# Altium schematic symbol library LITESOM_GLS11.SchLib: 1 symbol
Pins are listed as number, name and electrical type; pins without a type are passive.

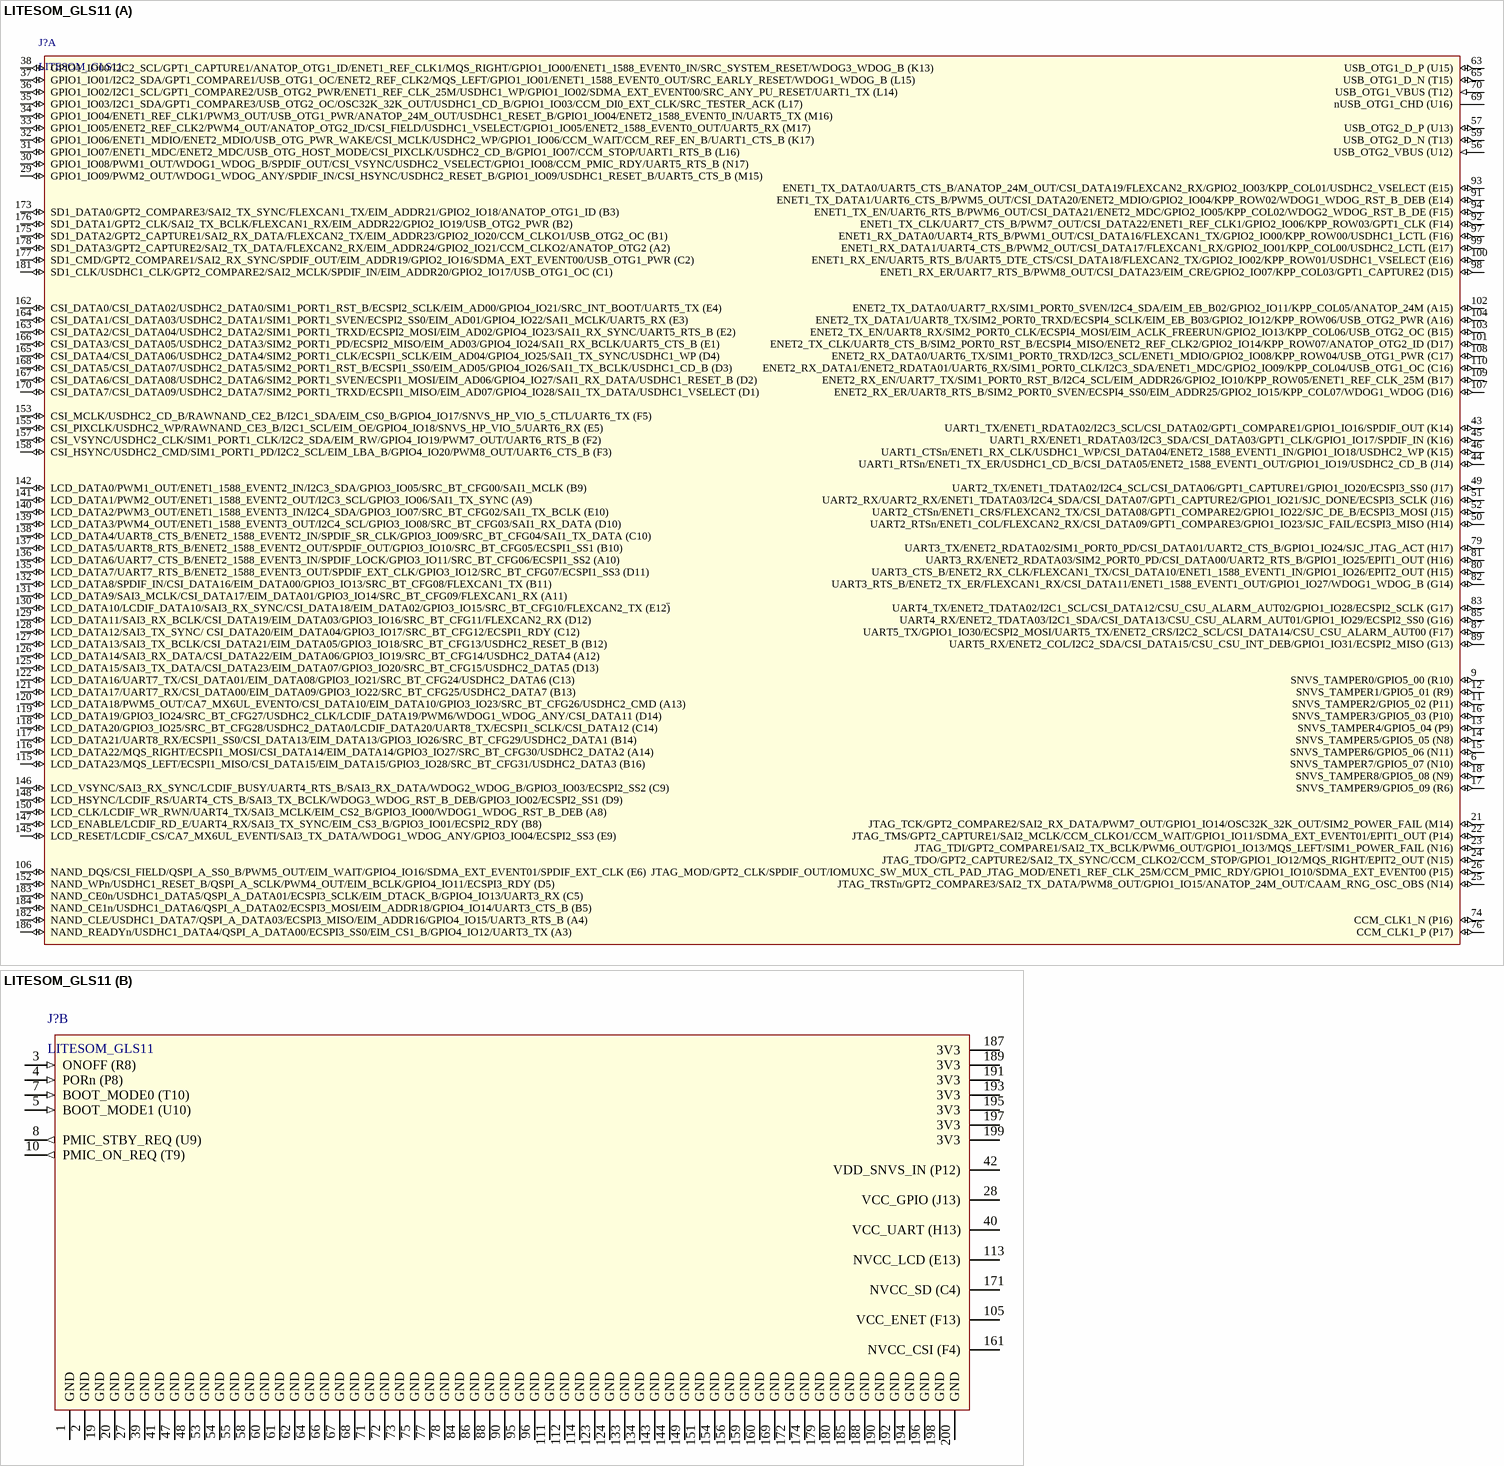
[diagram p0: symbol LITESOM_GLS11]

## LITESOM_GLS11
designator J?
part A pins: 6 SNVS_TAMPER7/GPIO5_07 (N10) (io), 9 SNVS_TAMPER0/GPIO5_00 (R10) (io), 11 SNVS_TAMPER2/GPIO5_02 (P11) (io), 12 SNVS_TAMPER1/GPIO5_01 (R9) (io), 13 SNVS_TAMPER4/GPIO5_04 (P9) (io), 14 SNVS_TAMPER5/GPIO5_05 (N8) (io), 15 SNVS_TAMPER6/GPIO5_06 (N11) (io), 16 SNVS_TAMPER3/GPIO5_03 (P10) (io), 17 SNVS_TAMPER9/GPIO5_09 (R6) (io), 18 SNVS_TAMPER8/GPIO5_08 (N9) (io), 21 JTAG_TCK/GPT2_COMPARE2/SAI2_RX_DATA/PWM7_OUT/GPIO1_IO14/OSC32K_32K_OUT/SIM2_POWER_FAIL (M14) (io), 22 JTAG_TMS/GPT2_CAPTURE1/SAI2_MCLK/CCM_CLKO1/CCM_WAIT/GPIO1_IO11/SDMA_EXT_EVENT01/EPIT1_OUT (P14) (io), 23 JTAG_TDI/GPT2_COMPARE1/SAI2_TX_BCLK/PWM6_OUT/GPIO1_IO13/MQS_LEFT/SIM1_POWER_FAIL (N16) (io), 24 JTAG_TDO/GPT2_CAPTURE2/SAI2_TX_SYNC/CCM_CLKO2/CCM_STOP/GPIO1_IO12/MQS_RIGHT/EPIT2_OUT (N15) (io), 25 JTAG_TRSTn/GPT2_COMPARE3/SAI2_TX_DATA/PWM8_OUT/GPIO1_IO15/ANATOP_24M_OUT/CAAM_RNG_OSC_OBS (N14) (io), 26 JTAG_MOD/GPT2_CLK/SPDIF_OUT/IOMUXC_SW_MUX_CTL_PAD_JTAG_MOD/ENET1_REF_CLK_25M/CCM_PMIC_RDY/GPIO1_IO10/SDMA_EXT_EVENT00 (P15) (io), 29 GPIO1_IO09/PWM2_OUT/WDOG1_WDOG_ANY/SPDIF_IN/CSI_HSYNC/USDHC2_RESET_B/GPIO1_IO09/USDHC1_RESET_B/UART5_CTS_B (M15) (io), 30 GPIO1_IO08/PWM1_OUT/WDOG1_WDOG_B/SPDIF_OUT/CSI_VSYNC/USDHC2_VSELECT/GPIO1_IO08/CCM_PMIC_RDY/UART5_RTS_B (N17) (io), 31 GPIO1_IO07/ENET1_MDC/ENET2_MDC/USB_OTG_HOST_MODE/CSI_PIXCLK/USDHC2_CD_B/GPIO1_IO07/CCM_STOP/UART1_RTS_B (L16) (io), 32 GPIO1_IO06/ENET1_MDIO/ENET2_MDIO/USB_OTG_PWR_WAKE/CSI_MCLK/USDHC2_WP/GPIO1_IO06/CCM_WAIT/CCM_REF_EN_B/UART1_CTS_B (K17) (io), 33 GPIO1_IO05/ENET2_REF_CLK2/PWM4_OUT/ANATOP_OTG2_ID/CSI_FIELD/USDHC1_VSELECT/GPIO1_IO05/ENET2_1588_EVENT0_OUT/UART5_RX (M17) (io), 34 GPIO1_IO04/ENET1_REF_CLK1/PWM3_OUT/USB_OTG1_PWR/ANATOP_24M_OUT/USDHC1_RESET_B/GPIO1_IO04/ENET2_1588_EVENT0_IN/UART5_TX (M16) (io), 35 GPIO1_IO03/I2C1_SDA/GPT1_COMPARE3/USB_OTG2_OC/OSC32K_32K_OUT/USDHC1_CD_B/GPIO1_IO03/CCM_DI0_EXT_CLK/SRC_TESTER_ACK (L17) (io), 36 GPIO1_IO02/I2C1_SCL/GPT1_COMPARE2/USB_OTG2_PWR/ENET1_REF_CLK_25M/USDHC1_WP/GPIO1_IO02/SDMA_EXT_EVENT00/SRC_ANY_PU_RESET/UART1_TX (L14) (io), 37 GPIO1_IO01/I2C2_SDA/GPT1_COMPARE1/USB_OTG1_OC/ENET2_REF_CLK2/MQS_LEFT/GPIO1_IO01/ENET1_1588_EVENT0_OUT/SRC_EARLY_RESET/WDOG1_WDOG_B (L15) (io), 38 GPIO1_IO00/I2C2_SCL/GPT1_CAPTURE1/ANATOP_OTG1_ID/ENET1_REF_CLK1/MQS_RIGHT/GPIO1_IO00/ENET1_1588_EVENT0_IN/SRC_SYSTEM_RESET/WDOG3_WDOG_B (K13) (io), 43 UART1_TX/ENET1_RDATA02/I2C3_SCL/CSI_DATA02/GPT1_COMPARE1/GPIO1_IO16/SPDIF_OUT (K14) (io), 44 UART1_RTSn/ENET1_TX_ER/USDHC1_CD_B/CSI_DATA05/ENET2_1588_EVENT1_OUT/GPIO1_IO19/USDHC2_CD_B (J14) (io), 45 UART1_RX/ENET1_RDATA03/I2C3_SDA/CSI_DATA03/GPT1_CLK/GPIO1_IO17/SPDIF_IN (K16) (io), 46 UART1_CTSn/ENET1_RX_CLK/USDHC1_WP/CSI_DATA04/ENET2_1588_EVENT1_IN/GPIO1_IO18/USDHC2_WP (K15) (io), 49 UART2_TX/ENET1_TDATA02/I2C4_SCL/CSI_DATA06/GPT1_CAPTURE1/GPIO1_IO20/ECSPI3_SS0 (J17) (io), 50 UART2_RTSn/ENET1_COL/FLEXCAN2_RX/CSI_DATA09/GPT1_COMPARE3/GPIO1_IO23/SJC_FAIL/ECSPI3_MISO (H14) (io), 51 UART2_RX/UART2_RX/ENET1_TDATA03/I2C4_SDA/CSI_DATA07/GPT1_CAPTURE2/GPIO1_IO21/SJC_DONE/ECSPI3_SCLK (J16) (io), 52 UART2_CTSn/ENET1_CRS/FLEXCAN2_TX/CSI_DATA08/GPT1_COMPARE2/GPIO1_IO22/SJC_DE_B/ECSPI3_MOSI (J15) (io), 56 USB_OTG2_VBUS (U12) (in), 57 USB_OTG2_D_P (U13) (io), 59 USB_OTG2_D_N (T13) (io), 63 USB_OTG1_D_P (U15) (io), 65 USB_OTG1_D_N (T15) (io), 69 nUSB_OTG1_CHD (U16) (oc), 70 USB_OTG1_VBUS (T12) (in), 74 CCM_CLK1_N (P16) (io), 76 CCM_CLK1_P (P17) (io), 79 UART3_TX/ENET2_RDATA02/SIM1_PORT0_PD/CSI_DATA01/UART2_CTS_B/GPIO1_IO24/SJC_JTAG_ACT (H17) (io), 80 UART3_CTS_B/ENET2_RX_CLK/FLEXCAN1_TX/CSI_DATA10/ENET1_1588_EVENT1_IN/GPIO1_IO26/EPIT2_OUT (H15) (io), 81 UART3_RX/ENET2_RDATA03/SIM2_PORT0_PD/CSI_DATA00/UART2_RTS_B/GPIO1_IO25/EPIT1_OUT (H16) (io), 82 UART3_RTS_B/ENET2_TX_ER/FLEXCAN1_RX/CSI_DATA11/ENET1_1588_EVENT1_OUT/GPIO1_IO27/WDOG1_WDOG_B (G14) (io), 83 UART4_TX/ENET2_TDATA02/I2C1_SCL/CSI_DATA12/CSU_CSU_ALARM_AUT02/GPIO1_IO28/ECSPI2_SCLK (G17) (io), 85 UART4_RX/ENET2_TDATA03/I2C1_SDA/CSI_DATA13/CSU_CSU_ALARM_AUT01/GPIO1_IO29/ECSPI2_SS0 (G16) (io), 87 UART5_TX/GPIO1_IO30/ECSPI2_MOSI/UART5_TX/ENET2_CRS/I2C2_SCL/CSI_DATA14/CSU_CSU_ALARM_AUT00 (F17) (io), 89 UART5_RX/ENET2_COL/I2C2_SDA/CSI_DATA15/CSU_CSU_INT_DEB/GPIO1_IO31/ECSPI2_MISO (G13) (io), 91 ENET1_TX_DATA1/UART6_CTS_B/PWM5_OUT/CSI_DATA20/ENET2_MDIO/GPIO2_IO04/KPP_ROW02/WDOG1_WDOG_RST_B_DEB (E14) (io), 92 ENET1_TX_CLK/UART7_CTS_B/PWM7_OUT/CSI_DATA22/ENET1_REF_CLK1/GPIO2_IO06/KPP_ROW03/GPT1_CLK (F14) (io), 93 ENET1_TX_DATA0/UART5_CTS_B/ANATOP_24M_OUT/CSI_DATA19/FLEXCAN2_RX/GPIO2_IO03/KPP_COL01/USDHC2_VSELECT (E15) (io), 94 ENET1_TX_EN/UART6_RTS_B/PWM6_OUT/CSI_DATA21/ENET2_MDC/GPIO2_IO05/KPP_COL02/WDOG2_WDOG_RST_B_DE (F15) (io), 97 ENET1_RX_DATA0/UART4_RTS_B/PWM1_OUT/CSI_DATA16/FLEXCAN1_TX/GPIO2_IO00/KPP_ROW00/USDHC1_LCTL (F16) (io), 98 ENET1_RX_ER/UART7_RTS_B/PWM8_OUT/CSI_DATA23/EIM_CRE/GPIO2_IO07/KPP_COL03/GPT1_CAPTURE2 (D15) (io), 99 ENET1_RX_DATA1/UART4_CTS_B/PWM2_OUT/CSI_DATA17/FLEXCAN1_RX/GPIO2_IO01/KPP_COL00/USDHC2_LCTL (E17) (io), 100 ENET1_RX_EN/UART5_RTS_B/UART5_DTE_CTS/CSI_DATA18/FLEXCAN2_TX/GPIO2_IO02/KPP_ROW01/USDHC1_VSELECT (E16) (io), 101 ENET2_TX_CLK/UART8_CTS_B/SIM2_PORT0_RST_B/ECSPI4_MISO/ENET2_REF_CLK2/GPIO2_IO14/KPP_ROW07/ANATOP_OTG2_ID (D17) (io), 102 ENET2_TX_DATA0/UART7_RX/SIM1_PORT0_SVEN/I2C4_SDA/EIM_EB_B02/GPIO2_IO11/KPP_COL05/ANATOP_24M (A15) (io), 103 ENET2_TX_EN/UART8_RX/SIM2_PORT0_CLK/ECSPI4_MOSI/EIM_ACLK_FREERUN/GPIO2_IO13/KPP_COL06/USB_OTG2_OC (B15) (io), 104 ENET2_TX_DATA1/UART8_TX/SIM2_PORT0_TRXD/ECSPI4_SCLK/EIM_EB_B03/GPIO2_IO12/KPP_ROW06/USB_OTG2_PWR (A16) (io), 106 NAND_DQS/CSI_FIELD/QSPI_A_SS0_B/PWM5_OUT/EIM_WAIT/GPIO4_IO16/SDMA_EXT_EVENT01/SPDIF_EXT_CLK (E6) (io), 107 ENET2_RX_ER/UART8_RTS_B/SIM2_PORT0_SVEN/ECSPI4_SS0/EIM_ADDR25/GPIO2_IO15/KPP_COL07/WDOG1_WDOG (D16) (io), 108 ENET2_RX_DATA0/UART6_TX/SIM1_PORT0_TRXD/I2C3_SCL/ENET1_MDIO/GPIO2_IO08/KPP_ROW04/USB_OTG1_PWR (C17) (io), 109 ENET2_RX_EN/UART7_TX/SIM1_PORT0_RST_B/I2C4_SCL/EIM_ADDR26/GPIO2_IO10/KPP_ROW05/ENET1_REF_CLK_25M (B17) (io), 110 ENET2_RX_DATA1/ENET2_RDATA01/UART6_RX/SIM1_PORT0_CLK/I2C3_SDA/ENET1_MDC/GPIO2_IO09/KPP_COL04/USB_OTG1_OC (C16) (io), 115 LCD_DATA23/MQS_LEFT/ECSPI1_MISO/CSI_DATA15/EIM_DATA15/GPIO3_IO28/SRC_BT_CFG31/USDHC2_DATA3 (B16) (io), 116 LCD_DATA22/MQS_RIGHT/ECSPI1_MOSI/CSI_DATA14/EIM_DATA14/GPIO3_IO27/SRC_BT_CFG30/USDHC2_DATA2 (A14) (io), 117 LCD_DATA21/UART8_RX/ECSPI1_SS0/CSI_DATA13/EIM_DATA13/GPIO3_IO26/SRC_BT_CFG29/USDHC2_DATA1 (B14) (io), 118 LCD_DATA20/GPIO3_IO25/SRC_BT_CFG28/USDHC2_DATA0/LCDIF_DATA20/UART8_TX/ECSPI1_SCLK/CSI_DATA12 (C14) (io), 119 LCD_DATA19/GPIO3_IO24/SRC_BT_CFG27/USDHC2_CLK/LCDIF_DATA19/PWM6/WDOG1_WDOG_ANY/CSI_DATA11 (D14) (io), 120 LCD_DATA18/PWM5_OUT/CA7_MX6UL_EVENTO/CSI_DATA10/EIM_DATA10/GPIO3_IO23/SRC_BT_CFG26/USDHC2_CMD (A13) (io), 121 LCD_DATA17/UART7_RX/CSI_DATA00/EIM_DATA09/GPIO3_IO22/SRC_BT_CFG25/USDHC2_DATA7 (B13) (io), 122 LCD_DATA16/UART7_TX/CSI_DATA01/EIM_DATA08/GPIO3_IO21/SRC_BT_CFG24/USDHC2_DATA6 (C13) (io), 125 LCD_DATA15/SAI3_TX_DATA/CSI_DATA23/EIM_DATA07/GPIO3_IO20/SRC_BT_CFG15/USDHC2_DATA5 (D13) (io), 126 LCD_DATA14/SAI3_RX_DATA/CSI_DATA22/EIM_DATA06/GPIO3_IO19/SRC_BT_CFG14/USDHC2_DATA4 (A12) (io), 127 LCD_DATA13/SAI3_TX_BCLK/CSI_DATA21/EIM_DATA05/GPIO3_IO18/SRC_BT_CFG13/USDHC2_RESET_B (B12) (io), 128 LCD_DATA12/SAI3_TX_SYNC/ CSI_DATA20/EIM_DATA04/GPIO3_IO17/SRC_BT_CFG12/ECSPI1_RDY (C12) (io), 129 LCD_DATA11/SAI3_RX_BCLK/CSI_DATA19/EIM_DATA03/GPIO3_IO16/SRC_BT_CFG11/FLEXCAN2_RX (D12) (io), 130 LCD_DATA10/LCDIF_DATA10/SAI3_RX_SYNC/CSI_DATA18/EIM_DATA02/GPIO3_IO15/SRC_BT_CFG10/FLEXCAN2_TX (E12~{)} (io), 131 LCD_DATA9/SAI3_MCLK/CSI_DATA17/EIM_DATA01/GPIO3_IO14/SRC_BT_CFG09/FLEXCAN1_RX (A11) (io), 132 LCD_DATA8/SPDIF_IN/CSI_DATA16/EIM_DATA00/GPIO3_IO13/SRC_BT_CFG08/FLEXCAN1_TX (B11) (io), 135 LCD_DATA7/UART7_RTS_B/ENET2_1588_EVENT3_OUT/SPDIF_EXT_CLK/GPIO3_IO12/SRC_BT_CFG07/ECSPI1_SS3 (D11) (io), 136 LCD_DATA6/UART7_CTS_B/ENET2_1588_EVENT3_IN/SPDIF_LOCK/GPIO3_IO11/SRC_BT_CFG06/ECSPI1_SS2 (A10) (io), 137 LCD_DATA5/UART8_RTS_B/ENET2_1588_EVENT2_OUT/SPDIF_OUT/GPIO3_IO10/SRC_BT_CFG05/ECSPI1_SS1 (B10) (io), 138 LCD_DATA4/UART8_CTS_B/ENET2_1588_EVENT2_IN/SPDIF_SR_CLK/GPIO3_IO09/SRC_BT_CFG04/SAI1_TX_DATA (C10) (io), 139 LCD_DATA3/PWM4_OUT/ENET1_1588_EVENT3_OUT/I2C4_SCL/GPIO3_IO08/SRC_BT_CFG03/SAI1_RX_DATA (D10) (io), 140 LCD_DATA2/PWM3_OUT/ENET1_1588_EVENT3_IN/I2C4_SDA/GPIO3_IO07/SRC_BT_CFG02/SAI1_TX_BCLK (E10) (io), 141 LCD_DATA1/PWM2_OUT/ENET1_1588_EVENT2_OUT/I2C3_SCL/GPIO3_IO06/SAI1_TX_SYNC (A9) (io), 142 LCD_DATA0/PWM1_OUT/ENET1_1588_EVENT2_IN/I2C3_SDA/GPIO3_IO05/SRC_BT_CFG00/SAI1_MCLK (B9) (io), 145 LCD_RESET/LCDIF_CS/CA7_MX6UL_EVENTI/SAI3_TX_DATA/WDOG1_WDOG_ANY/GPIO3_IO04/ECSPI2_SS3 (E9) (io), 146 LCD_VSYNC/SAI3_RX_SYNC/LCDIF_BUSY/UART4_RTS_B/SAI3_RX_DATA/WDOG2_WDOG_B/GPIO3_IO03/ECSPI2_SS2 (C9) (io), 147 LCD_ENABLE/LCDIF_RD_E/UART4_RX/SAI3_TX_SYNC/EIM_CS3_B/GPIO3_IO01/ECSPI2_RDY (B8) (io), 148 LCD_HSYNC/LCDIF_RS/UART4_CTS_B/SAI3_TX_BCLK/WDOG3_WDOG_RST_B_DEB/GPIO3_IO02/ECSPI2_SS1 (D9) (io), 150 LCD_CLK/LCDIF_WR_RWN/UART4_TX/SAI3_MCLK/EIM_CS2_B/GPIO3_IO00/WDOG1_WDOG_RST_B_DEB (A8) (io), 152 NAND_WPn/USDHC1_RESET_B/QSPI_A_SCLK/PWM4_OUT/EIM_BCLK/GPIO4_IO11/ECSPI3_RDY (D5) (io), 153 CSI_MCLK/USDHC2_CD_B/RAWNAND_CE2_B/I2C1_SDA/EIM_CS0_B/GPIO4_IO17/SNVS_HP_VIO_5_CTL/UART6_TX (F5) (io), 155 CSI_PIXCLK/USDHC2_WP/RAWNAND_CE3_B/I2C1_SCL/EIM_OE/GPIO4_IO18/SNVS_HP_VIO_5/UART6_RX (E5) (io), 157 CSI_VSYNC/USDHC2_CLK/SIM1_PORT1_CLK/I2C2_SDA/EIM_RW/GPIO4_IO19/PWM7_OUT/UART6_RTS_B (F2) (io), 158 CSI_HSYNC/USDHC2_CMD/SIM1_PORT1_PD/I2C2_SCL/EIM_LBA_B/GPIO4_IO20/PWM8_OUT/UART6_CTS_B (F3) (io), 162 CSI_DATA0/CSI_DATA02/USDHC2_DATA0/SIM1_PORT1_RST_B/ECSPI2_SCLK/EIM_AD00/GPIO4_IO21/SRC_INT_BOOT/UART5_TX (E4) (io), 163 CSI_DATA2/CSI_DATA04/USDHC2_DATA2/SIM1_PORT1_TRXD/ECSPI2_MOSI/EIM_AD02/GPIO4_IO23/SAI1_RX_SYNC/UART5_RTS_B (E2) (io), 164 CSI_DATA1/CSI_DATA03/USDHC2_DATA1/SIM1_PORT1_SVEN/ECSPI2_SS0/EIM_AD01/GPIO4_IO22/SAI1_MCLK/UART5_RX (E3) (io), 165 CSI_DATA4/CSI_DATA06/USDHC2_DATA4/SIM2_PORT1_CLK/ECSPI1_SCLK/EIM_AD04/GPIO4_IO25/SAI1_TX_SYNC/USDHC1_WP (D4) (io), 166 CSI_DATA3/CSI_DATA05/USDHC2_DATA3/SIM2_PORT1_PD/ECSPI2_MISO/EIM_AD03/GPIO4_IO24/SAI1_RX_BCLK/UART5_CTS_B (E1) (io), 167 CSI_DATA6/CSI_DATA08/USDHC2_DATA6/SIM2_PORT1_SVEN/ECSPI1_MOSI/EIM_AD06/GPIO4_IO27/SAI1_RX_DATA/USDHC1_RESET_B (D2) (io), 168 CSI_DATA5/CSI_DATA07/USDHC2_DATA5/SIM2_PORT1_RST_B/ECSPI1_SS0/EIM_AD05/GPIO4_IO26/SAI1_TX_BCLK/USDHC1_CD_B (D3) (io), 170 CSI_DATA7/CSI_DATA09/USDHC2_DATA7/SIM2_PORT1_TRXD/ECSPI1_MISO/EIM_AD07/GPIO4_IO28/SAI1_TX_DATA/USDHC1_VSELECT (D1) (io), 173 SD1_DATA0/GPT2_COMPARE3/SAI2_TX_SYNC/FLEXCAN1_TX/EIM_ADDR21/GPIO2_IO18/ANATOP_OTG1_ID (B3) (io), 175 SD1_DATA2/GPT2_CAPTURE1/SAI2_RX_DATA/FLEXCAN2_TX/EIM_ADDR23/GPIO2_IO20/CCM_CLKO1/USB_OTG2_OC (B1) (io), 176 SD1_DATA1/GPT2_CLK/SAI2_TX_BCLK/FLEXCAN1_RX/EIM_ADDR22/GPIO2_IO19/USB_OTG2_PWR (B2) (io), 177 SD1_CMD/GPT2_COMPARE1/SAI2_RX_SYNC/SPDIF_OUT/EIM_ADDR19/GPIO2_IO16/SDMA_EXT_EVENT00/USB_OTG1_PWR (C2) (io), 178 SD1_DATA3/GPT2_CAPTURE2/SAI2_TX_DATA/FLEXCAN2_RX/EIM_ADDR24/GPIO2_IO21/CCM_CLKO2/ANATOP_OTG2 (A2) (io), 181 SD1_CLK/USDHC1_CLK/GPT2_COMPARE2/SAI2_MCLK/SPDIF_IN/EIM_ADDR20/GPIO2_IO17/USB_OTG1_OC (C1) (io), 182 NAND_CLE/USDHC1_DATA7/QSPI_A_DATA03/ECSPI3_MISO/EIM_ADDR16/GPIO4_IO15/UART3_RTS_B (A4) (io), 183 NAND_CE0n/USDHC1_DATA5/QSPI_A_DATA01/ECSPI3_SCLK/EIM_DTACK_B/GPIO4_IO13/UART3_RX (C5) (io), 184 NAND_CE1n/USDHC1_DATA6/QSPI_A_DATA02/ECSPI3_MOSI/EIM_ADDR18/GPIO4_IO14/UART3_CTS_B (B5) (io), 186 NAND_READYn/USDHC1_DATA4/QSPI_A_DATA00/ECSPI3_SS0/EIM_CS1_B/GPIO4_IO12/UART3_TX (A3) (io)
part B pins: 1 GND (power), 2 GND (power), 3 ONOFF (R8) (in), 4 PORn (P8) (in), 5 BOOT_MODE1 (U10) (in), 7 BOOT_MODE0 (T10) (in), 8 PMIC_STBY_REQ (U9) (out), 10 PMIC_ON_REQ (T9) (out), 19 GND (power), 20 GND (power), 27 GND (power), 28 VCC_GPIO (J13) (power), 39 GND (power), 40 VCC_UART (H13) (power), 41 GND (power), 42 VDD_SNVS_IN (P12) (power), 47 GND (power), 48 GND (power), 53 GND (power), 54 GND (power), 55 GND (power), 58 GND (power), 60 GND (power), 61 GND (power), 62 GND (power), 64 GND (power), 66 GND (power), 67 GND (power), 68 GND (power), 71 GND (power), 72 GND (power), 73 GND (power), 75 GND (power), 77 GND (power), 78 GND (power), 84 GND (power), 86 GND (power), 88 GND (power), 90 GND (power), 95 GND (power), 96 GND (power), 105 VCC_ENET (F13) (power), 111 GND (power), 112 GND (power), 113 NVCC_LCD (E13) (power), 114 GND (power), 123 GND (power), 124 GND (power), 133 GND (power), 134 GND (power), 143 GND (power), 144 GND (power), 149 GND (power), 151 GND (power), 154 GND (power), 156 GND (power), 159 GND (power), 160 GND (power), 161 NVCC_CSI (F4) (power), 169 GND (power), 171 NVCC_SD (C4) (power), 172 GND (power), 174 GND (power), 179 GND (power), 180 GND (power), 185 GND (power), 187 3V3 (power), 188 GND (power), 189 3V3 (power), 190 GND (power), 191 3V3 (power), 192 GND (power), 193 3V3 (power), 194 GND (power), 195 3V3 (power), 196 GND (power), 197 3V3 (power), 198 GND (power), 199 3V3 (power), 200 GND (power)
